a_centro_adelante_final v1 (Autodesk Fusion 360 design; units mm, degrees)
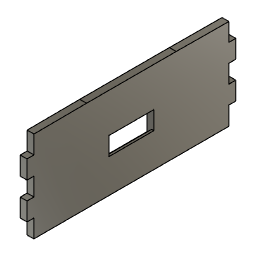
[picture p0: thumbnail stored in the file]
sketch "Sketch1" plane through (0, 0, 0) normal (1, 0, 0) x axis (0, 1, 0)
  line L1 (15, 0) -> (444.8, 0)
  line L2 (15.2, 160.15) -> (15.2, 200)
  line L3 (0, 160.15) -> (15.2, 160.15)
  line L4 (0, 119.6381) -> (15.2, 119.6381)
  line L5 (15.2, 79.7881) -> (0, 79.7881)
  line L6 (15.2, 119.6381) -> (15.2, 79.7881)
  line L7 (444.8, 160.15) -> (460, 160.15)
  line L8 (460, 120.3) -> (444.8, 120.3)
  line L9 (460, 160.15) -> (460, 120.3)
  line L10 (444.8, 160.15) -> (444.8, 200)
  line L11 (460, 160.15) -> (444.8, 160.15)
  line L12 (444.8, 120.3) -> (460, 120.3)
  line L13 (444.8, 80.45) -> (444.8, 120.3)
  line L14 (460, 80.45) -> (444.8, 80.45)
  line L15 (444.8, 200) -> (328.7889, 200.8074)
  line L16 (460, 120.3) -> (460, 160.15)
  line L17 (460, 40.6) -> (460, 80.45)
  line L18 (15.2, 160.15) -> (15.2, 200)
  line L19 (0, 160.15) -> (15.2, 160.15)
  line L20 (0, 79.7881) -> (0, 39.894)
  line L21 (0, 160.15) -> (0, 119.6381)
  line L22 (15, 39.894) -> (0, 39.894)
  line L23 (15, 0) -> (15, 39.894)
  line L24 (0, 0) -> (15, 0)
  line L25 (444.8, 80.45) -> (460, 80.45)
  line L26 (460, 40.6) -> (444.8, 40.6)
  line L27 (460, 80.45) -> (460, 40.6)
  line L28 (460, 40.6) -> (444.8, 40.6)
  line L29 (444.8, 40.6) -> (444.8, 0)
  line L30 (131.2111, 200.8074) -> (15.2, 200)
  line L31 (279.5, 64.4277) -> (180.5, 124.4277)
  line L32 (180.5, 64.4277) -> (279.5, 124.4277)
  line L33 (279.5, 114.5277) -> (180.5, 114.5277)
  line L34 (279.5, 74.3277) -> (279.5, 114.5277)
  line L35 (180.5, 74.3277) -> (279.5, 74.3277)
  line L36 (180.5, 114.5277) -> (180.5, 74.3277)
  line L37 (279.5, 74.3277) -> (180.5, 114.5277)
  line L38 (180.5, 74.3277) -> (279.5, 114.5277)
  line L39 (131.2111, 200.8074) -> (328.7889, 200.8074)
  point P35 (230, 94.4277)
  point P40 (230, 94.4277)
  point P7 (15.2, 119.6381)
  point P10 (15.2, 79.7881)
  point P11 (460, 160.15)
  point P12 (444.8, 160.15)
  point P14 (460, 120.3)
  point P19 (460, 80.45)
  point P26 (444.8, 80.45)
  point P28 (460, 40.6)
  point P37 (279.5, 114.5277)
  point P38 (279.5, 74.3277)
  horizontal L1
  vertical L20
  vertical L2
  horizontal L3
  horizontal L4
  horizontal L5
  vertical L6
  horizontal L7
  horizontal L8
  vertical L9
  vertical L10
  horizontal L11
  horizontal L12
  vertical L13
  horizontal L14
  collinear L16 L17
  vertical L18
  horizontal L19
  collinear L20 L21
  horizontal L22
  vertical L23
  horizontal L24
  horizontal L25
  horizontal L26
  vertical L27
  horizontal L28
  vertical L29
  coincident L31 P35
  coincident L32 P35
  horizontal L33
  perpendicular L33 L34
  parallel L33 L35
  parallel L34 L36
  coincident L37 P40
  coincident L38 P40
  coincident P35 P40
  horizontal L39
  dimension "d10" distance P7 P10 = 39.85
  dimension "d11" distance P11 P12 = 15.2
  dimension "d14" distance P14 P19 = 39.85
  dimension "d15" distance P19 P26 = 15.2
  dimension "d16" distance P19 P28 = 39.85
  dimension "d22" distance P37 P38 = 40.2
extrude "Extrude1" new body sketch "Sketch1" profile of L17 L1 L21 L2 L3 L4 L5 L6 L7 L8 L9 L10 L11 L12 L13 L14 L15 L18 L19 L22 L23 L25 L26 L27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 along normal blind 15
extrude "Extrude2" cut sketch "Sketch1" profile of L33 L34 L35 L36 along normal blind 20
sketch "Sketch2" plane through (0, 0, 0) normal (1, 0, 0) x axis (0, 1, 0)
  line L1 (180.5, 125) -> (279.5, 125)
  line L2 (279.5, 65) -> (180.5, 65)
  line L3 (279.5, 125) -> (279.5, 65)
  line L4 (180.5, 65) -> (279.5, 125)
  line L5 (279.5, 65) -> (180.5, 125)
  line L6 (180.5, 65) -> (180.5, 125)
  point P6 (230, 95)
  point P4 (180.5, 65)
  point P5 (279.5, 65)
  point P3 (180.5, 125)
  horizontal L1
  parallel L1 L2
  coincident L4 P6
  coincident L5 P6
  perpendicular L1 L6
  dimension "d25" distance P4 P5 = 99
  dimension "d26" distance P3 P4 = 60
extrude "Extrude3" cut sketch "Sketch2" profile of L1 L2 L3 L6 along normal blind 10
